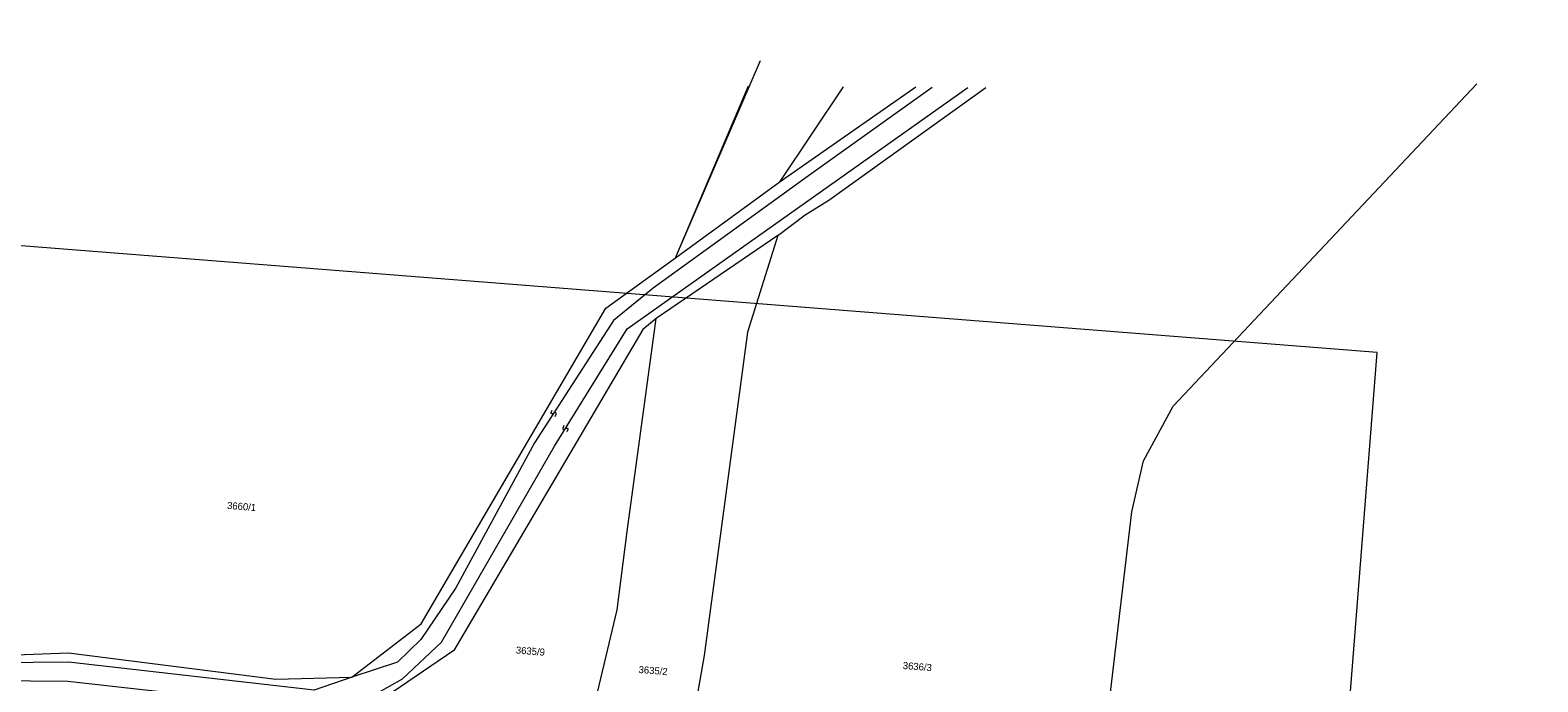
# Model space of a CAD drawing. Extents: x -686682 to -685519, y -959675 to -959188.
# Drawn here: x -685922.2 to -685518.7, y -959362.9 to -959188.4 of the extents above; entities that cross this region are included whole.
import ezdxf

# ---------------------------------------------------------------- set-up
doc = ezdxf.new("R2010")
doc.units = 0
doc.header["$LTSCALE"] = 0.76
doc.layers.add('1', color=7, linetype='Continuous', lineweight=13)

msp = doc.modelspace()

# ---------------------------------------------------------------- linework, layer by layer
at = {"layer": '1'}
for p, q in [((-685749.54, -959249.37), (-685726.74, -959196.55)), ((-685749.54, -959249.37), (-685729.937, -959203.338)), ((-685721.51, -959228.95), (-685685.181, -959203.641))]:
    msp.add_line(p, q, dxfattribs=at)
msp.add_lwpolyline([(-686681.662, -959484.53), (-685585.053, -959570.835), (-685561.751, -959274.75), (-686658.36, -959188.445)], close=True, dxfattribs=at)
for points in [[(-685518.73, -959475.43), (-685550.51, -959463.84), (-685579.91, -959458.16), (-685593.62, -959455.61), (-685642, -959441.26), (-685627.4, -959317.37), (-685624.29, -959303.78), (-685616.36, -959289.13), (-685535.037, -959202.809)], [(-686204.063, -959379.791), (-686066.016, -959368.791), (-685932.223, -959362.514), (-685912.138, -959362.723), (-685853.767, -959369.209), (-685840.377, -959369), (-685833.055, -959367.954), (-685822.594, -959362.096), (-685812.133, -959352.263), (-685781.902, -959299.854), (-685762.445, -959268.42), (-685671.271, -959203.792)], [(-685680.796, -959203.792), (-685713.942, -959227.414), (-685755.506, -959257.541), (-685766.106, -959266.188), (-685787.237, -959298.93), (-685808.263, -959337.775), (-685817.678, -959351.583), (-685823.954, -959357.65), (-685836.161, -959361.703), (-685846.235, -959365.182), (-685911.929, -959357.65), (-685930.968, -959357.859), (-686094.888, -959365.809), (-686195.703, -959372.289)], [(-685942.56, -959356.28), (-685911.931, -959355.103), (-685856.49, -959362.231), (-685836.161, -959361.703), (-685817.548, -959347.38), (-685768.179, -959262.832), (-685749.54, -959249.37), (-685721.51, -959228.95), (-685704.535, -959203.641)], [(-685722.14, -959243.4), (-685714.849, -959237.883), (-685708.513, -959233.923), (-685666.432, -959203.792)], [(-685722.14, -959243.4), (-685754.66, -959265.62), (-685758.278, -959268.574), (-685808.836, -959354.509), (-685831.277, -959369.821), (-685859.16, -959372.33)], [(-685722.14, -959243.4), (-685730.28, -959269.26), (-685741.85, -959355.88), (-685749.6, -959400)], [(-685749.6, -959400), (-685776.9, -959393.16), (-685765.13, -959343.64), (-685762.47, -959322.7), (-685754.66, -959265.62)], [(-685781.732, -959291.877), (-685781.437, -959291.234), (-685781.496, -959290.958), (-685781.665, -959290.849), (-685781.941, -959290.909), (-685782.326, -959291.136), (-685782.602, -959291.196), (-685782.77, -959291.088), (-685782.83, -959290.811), (-685782.535, -959290.169)], [(-685779.41, -959294.308), (-685779.693, -959294.956), (-685779.628, -959295.231), (-685779.458, -959295.337), (-685779.183, -959295.272), (-685778.803, -959295.037), (-685778.527, -959294.972), (-685778.357, -959295.078), (-685778.292, -959295.353), (-685778.576, -959296.001)]]:
    msp.add_lwpolyline(points, dxfattribs=at)

# ---------------------------------------------------------------- texts
for s, p in [('3660/1', (-685869.582, -959316.597)), ('3635/9', (-685792.297, -959355.328)), ('3635/2', (-685759.453, -959360.535)), ('3636/3', (-685688.742, -959359.463))]:
    msp.add_text(s, height=1.9, rotation=355.5, dxfattribs=at).set_placement(p)

doc.saveas('drawing.dxf')
